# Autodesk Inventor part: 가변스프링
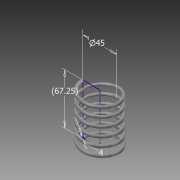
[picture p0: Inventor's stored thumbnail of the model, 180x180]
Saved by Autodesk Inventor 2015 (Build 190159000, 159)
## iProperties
Created: 2016-02
Part Number: 가변스프링
Material: 스테인레스 스틸
Document SubType Name: Modeling
Designer: Administrator
Mass: 84.1995 g
Surface Area: 106.448 cm^2
Volume: 10.5249 cm^3
Density: 8 g/cm^3
Appearance: 반연마
Author: Administrator
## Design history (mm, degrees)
sketch "스케치1"
  geometry: L1 (0, 0)-(22.5, 0); L2 (22.5, 0)-(22.5, 67.25); L3 (22.5, 67.25)-(0, 67.25); L4 (0, 67.25)-(0, 0); C1 r 2 at (22.5, 0)
  constraints: 8 end point, 2 parallel, 1 centre point, 1 coincident, 1 horizontal, 1 perpendicular
  dimensions: "d0" = 45 diameter of L2 L4; "d1" = 67.25 distance between parallel lines of L1 L3 (derived); "d2" = 4 diameter of C1
feature "코일1" sketch "스케치1" pitch "d3" = 10; turns "d5" = 6; dims "d4" = 67.25 (= d1), "d6" = 0, angle "d7" = 90 deg, angle "d8" = 90 deg, "d9" = 0, "d10" = 0
sketch "스케치2"
  geometry: L1 (-20.5, 0)-(-24.5, 0) reference; 1 further point
  constraints: 1 horizontal alignment
extrude "돌출1" cut sketch "스케치2" stored distance "d11" = 10; taper "d12" = 0 deg
node "작업 평면1"
sketch "스케치3"
  geometry: L1 (20.5, 0)-(24.5, 0) reference; 1 further point
  constraints: 1 horizontal alignment
extrude "돌출2" cut sketch "스케치3" stored distance "d13" = 10; taper "d14" = 0 deg
node "솔리드1"
node "절단 모서리 투영1"
node "절단 모서리 투영2"
